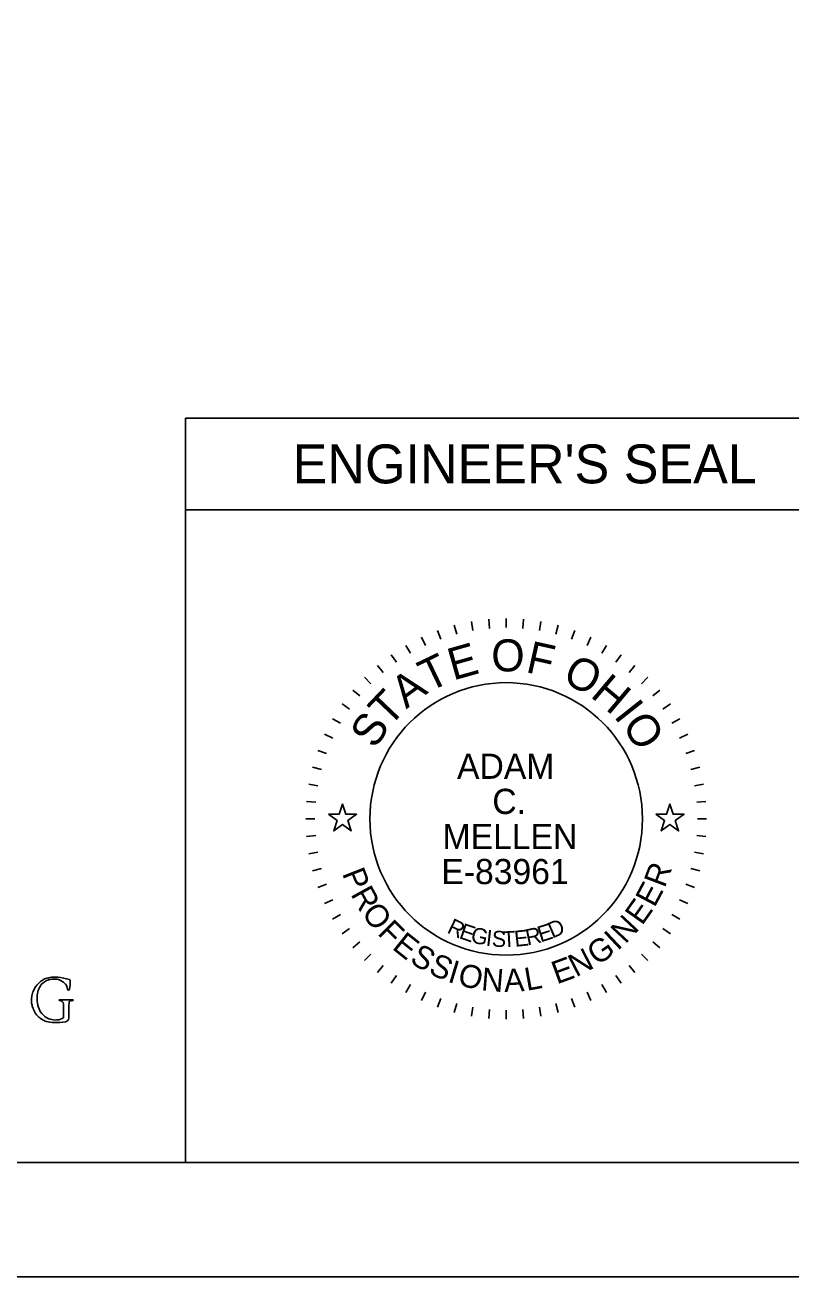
# Model space of a CAD drawing. Extents: x 0 to 34, y 0 to 22.
# Drawn here: x 6.65 to 9.99, y 0 to 5.47 of the extents above; entities that cross this region are included whole.
import ezdxf

# ---------------------------------------------------------------- set-up
doc = ezdxf.new("R2010")
doc.units = 0
for name, color, linetype in [('SH_Border', 7, 'Continuous'), ('SH_Cut_Line', 7, 'Continuous'), ('SH_Data', 7, 'Continuous'), ('SH_Seal', 7, 'Continuous'), ('SH_Text', 7, 'Continuous')]:
    doc.layers.add(name, color=color, linetype=linetype)

msp = doc.modelspace()

# ---------------------------------------------------------------- linework, layer by layer
at = {"layer": 'SH_Border'}
msp.add_lwpolyline([(1.5, 21.5), (33.5, 21.5), (33.5, 0.5), (1.5, 0.5)], close=True, dxfattribs=at)
at = {"layer": 'SH_Cut_Line'}
msp.add_lwpolyline([(0, 0), (34, 0), (34, 22), (0, 22)], close=True, dxfattribs=at)
at = {"layer": 'SH_Data'}
for p, q in [((10.15, 3.75), (7.35, 3.75)), ((7.35, 3.75), (7.35, 0.5)), ((10.15, 3.35), (7.35, 3.35)), ((10.15, 0.5), (7.35, 0.5))]:
    msp.add_line(p, q, dxfattribs=at)
at = {"layer": 'SH_Seal'}
for p, q in [((8.5235, 2.8452), (8.5339, 2.8065)), ((8.5981, 2.8617), (8.605, 2.8223)), ((8.6737, 2.8717), (8.6772, 2.8318)), ((8.75, 2.875), (8.75, 2.835)), ((8.8263, 2.8717), (8.8228, 2.8318)), ((8.9019, 2.8617), (8.895, 2.8223)), ((8.9765, 2.8452), (8.9661, 2.8065)), ((8.3802, 2.793), (8.3971, 2.7568)), ((8.4507, 2.8222), (8.4644, 2.7846)), ((9.0493, 2.8222), (9.0356, 2.7846)), ((9.1198, 2.793), (9.1029, 2.7568)), ((8.3125, 2.7578), (8.3325, 2.7231)), ((9.1875, 2.7578), (9.1675, 2.7231)), ((8.2481, 2.7168), (8.2711, 2.684)), ((9.2519, 2.7168), (9.2289, 2.684)), ((8.1876, 2.6703), (8.2133, 2.6396)), ((9.3124, 2.6703), (9.2867, 2.6396)), ((8.1313, 2.6187), (8.1596, 2.5904)), ((9.3687, 2.6187), (9.3404, 2.5904)), ((8.0797, 2.5624), (8.1104, 2.5367)), ((9.4203, 2.5624), (9.3896, 2.5367)), ((8.0332, 2.5019), (8.066, 2.4789)), ((9.4668, 2.5019), (9.434, 2.4789)), ((7.9922, 2.4375), (8.0269, 2.4175)), ((9.5078, 2.4375), (9.4731, 2.4175)), ((7.957, 2.3698), (7.9932, 2.3529)), ((9.543, 2.3698), (9.5068, 2.3529)), ((7.9278, 2.2993), (7.9654, 2.2856)), ((9.5722, 2.2993), (9.5346, 2.2856)), ((7.9048, 2.2265), (7.9435, 2.2161)), ((9.5952, 2.2265), (9.5565, 2.2161)), ((7.8883, 2.1519), (7.9277, 2.145)), ((9.6117, 2.1519), (9.5723, 2.145)), ((7.8783, 2.0763), (7.9182, 2.0728)), ((9.6217, 2.0763), (9.5818, 2.0728)), ((7.875, 2), (7.915, 2)), ((9.625, 2), (9.585, 2)), ((7.8783, 1.9237), (7.9182, 1.9272)), ((9.6217, 1.9237), (9.5818, 1.9272)), ((7.8883, 1.8481), (7.9277, 1.855)), ((9.6117, 1.8481), (9.5723, 1.855)), ((7.9048, 1.7735), (7.9435, 1.7839)), ((9.5952, 1.7735), (9.5565, 1.7839)), ((7.9278, 1.7007), (7.9654, 1.7144)), ((9.5722, 1.7007), (9.5346, 1.7144)), ((7.957, 1.6302), (7.9932, 1.6471)), ((9.543, 1.6302), (9.5068, 1.6471)), ((7.9922, 1.5625), (8.0269, 1.5825)), ((9.5078, 1.5625), (9.4731, 1.5825)), ((8.0332, 1.4981), (8.066, 1.5211)), ((9.4668, 1.4981), (9.434, 1.5211)), ((8.0797, 1.4376), (8.1104, 1.4633)), ((9.4203, 1.4376), (9.3896, 1.4633)), ((8.1313, 1.3813), (8.1596, 1.4096)), ((9.3687, 1.3813), (9.3404, 1.4096)), ((8.1876, 1.3297), (8.2133, 1.3604)), ((8.2481, 1.2832), (8.2711, 1.316)), ((9.2519, 1.2832), (9.2289, 1.316)), ((9.3124, 1.3297), (9.2867, 1.3604)), ((8.3125, 1.2422), (8.3325, 1.2769)), ((9.1875, 1.2422), (9.1675, 1.2769)), ((8.3802, 1.207), (8.3971, 1.2432)), ((8.4507, 1.1778), (8.4644, 1.2154)), ((9.0493, 1.1778), (9.0356, 1.2154)), ((9.1198, 1.207), (9.1029, 1.2432)), ((8.5235, 1.1548), (8.5339, 1.1935)), ((8.5981, 1.1383), (8.605, 1.1777)), ((8.6737, 1.1283), (8.6772, 1.1682)), ((8.75, 1.125), (8.75, 1.165)), ((8.8263, 1.1283), (8.8228, 1.1682)), ((8.9019, 1.1383), (8.895, 1.1777)), ((8.9765, 1.1548), (8.9661, 1.1935))]:
    msp.add_line(p, q, dxfattribs=at)
for points in [[(7.9736, 2.02), (8.0205, 2.02), (8.035, 2.0645), (8.0495, 2.02), (8.0964, 2.02), (8.0585, 1.9924), (8.073, 1.9478), (8.035, 1.9754), (7.997, 1.9478), (8.0115, 1.9924)], [(9.4036, 2.02), (9.4505, 2.02), (9.465, 2.0645), (9.4795, 2.02), (9.5264, 2.02), (9.4885, 1.9924), (9.503, 1.9478), (9.465, 1.9754), (9.427, 1.9478), (9.4415, 1.9924)]]:
    msp.add_lwpolyline(points, close=True, dxfattribs=at)
msp.add_circle((8.75, 2), 0.595, dxfattribs=at)
at = {"layer": 'SH_Text'}
for p, q in [((6.8573, 1.2104), (6.7998, 1.2104)), ((6.8165, 1.1919), (6.8165, 1.1358)), ((6.8402, 1.1303), (6.8402, 1.1778))]:
    msp.add_line(p, q, dxfattribs=at)
for centre, radius, start, end in [((6.7912, 1.2017), 0.1159, 135.2994, 157.2066), ((6.7747, 1.2302), 0.0714, 147.5385, 165.5071), ((6.7705, 1.2222), 0.0867, 107.613, 135.2994), ((6.7747, 1.2302), 0.0714, 116.7026, 147.5385), ((6.7691, 1.2414), 0.0589, 93.5922, 116.7026), ((6.772, 1.2175), 0.0916, 90.0889, 107.613), ((6.7762, 1.1283), 0.1722, 87.6816, 93.5922), ((6.7722, 1.0551), 0.254, 85.6243, 90.0889), ((6.7811, 1.2496), 0.0509, 59.809, 87.6816), ((6.773, 1.0659), 0.2432, 73.3259, 85.6243), ((6.7478, 1.1923), 0.1171, 52.0865, 59.809), ((6.7962, 1.2544), 0.0384, 2.9119, 52.0865), ((6.8414, 1.2941), 0.00494, 1.0594, 73.3259), ((6.6437, 1.2905), 0.2027, 350.1479, 1.0594), ((6.7684, 1.2065), 0.0913, 176.8679, 187.4835), ((6.8177, 1.2038), 0.1407, 167.8164, 176.8679), ((6.7472, 1.2191), 0.0685, 158.442, 167.8164), ((6.7912, 1.2017), 0.1159, 157.2066, 158.442), ((6.8436, 1.2139), 0.1422, 167.8795, 178.2857), ((6.7993, 1.2152), 0.0979, 178.2857, 190.5998), ((6.8104, 1.221), 0.1082, 165.5071, 167.8795), ((6.7998, 1.2084), 0.00203, 90, 277.32), ((6.8019, 1.1919), 0.0146, 0, 97.32), ((6.839, 1.2566), 0.00447, 182.9119, 350.1479), ((6.8475, 1.199), 0.00585, 114.8736, 172.0456), ((6.8552, 1.1824), 0.0242, 95.8947, 114.8736), ((6.8706, 1.0334), 0.174, 94.3316, 95.8947), ((6.8573, 1.2086), 0.00179, 274.3316, 90), ((6.7562, 1.2049), 0.0789, 187.4835, 199.5864), ((6.8236, 1.2289), 0.1505, 199.5864, 208.6065), ((6.763, 1.1959), 0.0815, 208.6065, 229.3453), ((6.934, 1.2404), 0.2349, 190.5998, 194.5022), ((6.7857, 1.202), 0.0818, 194.5022, 227.8932), ((6.9991, 1.1778), 0.1589, 172.0456, 180), ((6.7848, 1.2213), 0.1149, 229.3453, 237.7571), ((6.76, 1.182), 0.0686, 237.7571, 254.2366), ((6.7815, 1.1974), 0.0755, 227.8932, 268.7516), ((6.7779, 1.2453), 0.1343, 254.2366, 269.1033), ((6.7806, 1.4165), 0.3056, 269.1033, 278.6618), ((6.7815, 1.1969), 0.075, 268.7516, 293.6665), ((6.8083, 1.1358), 0.00829, 293.6665, 0), ((6.8242, 1.1303), 0.016, 278.6618, 0)]:
    msp.add_arc(centre, radius, start, end, dxfattribs=at)

# ---------------------------------------------------------------- texts
at = {"layer": 'SH_Data'}
msp.add_text("ENGINEER'S SEAL", height=0.17, dxfattribs=at).set_placement((7.8176, 3.465))
at = {"layer": 'SH_Seal'}
for s, height, rotation, p in [('E', 0.14, 15.7571, (8.5184, 2.6038)), ('O', 0.14, 359.7812, (8.6847, 2.6443)), ('F', 0.14, 347.4362, (8.8311, 2.6417)), ('T', 0.14, 25.7167, (8.4116, 2.5518)), ('O', 0.14, 332.2586, (8.9898, 2.6015)), ('A', 0.14, 36.4747, (8.3134, 2.4781)), ('H', 0.14, 319.9136, (9.1132, 2.5361)), ('T', 0.14, 46.4344, (8.2383, 2.3964)), ('I', 0.14, 308.367, (9.2165, 2.4483)), ('S', 0.14, 57.1924, (8.1781, 2.3014)), ('O', 0.14, 303.1491, (9.2521, 2.4089)), ('R', 0.1, 69.2322, (9.4419, 1.6954)), ('P', 0.1, 291.494, (8.0323, 1.7621)), ('R', 0.1, 298.7311, (8.069, 1.6717)), ('E', 0.1, 61.9951, (9.3976, 1.6098)), ('E', 0.1, 54.758, (9.3433, 1.5314)), ('O', 0.1, 306.4666, (8.1155, 1.5883)), ('F', 0.1, 314.7068, (8.1843, 1.4983)), ('R', 0.07, 334.487, (8.4875, 1.5051)), ('E', 0.07, 341.04, (8.5406, 1.4801)), ('E', 0.07, 17.6836, (8.8998, 1.4602)), ('D', 0.07, 23.3052, (8.951, 1.477)), ('N', 0.1, 47.0224, (9.2702, 1.4508)), ('E', 0.1, 321.4393, (8.2478, 1.4348)), ('G', 0.07, 347.4752, (8.5914, 1.4618)), ('I', 0.07, 353.7858, (8.6591, 1.4468)), ('S', 0.07, 356.8926, (8.6858, 1.4429)), ('T', 0.07, 3.0061, (8.7357, 1.4387)), ('E', 0.07, 6.0117, (8.7889, 1.4412)), ('R', 0.07, 11.9184, (8.8425, 1.4474)), ('G', 0.1, 35.0469, (9.1481, 1.357)), ('I', 0.1, 43.287, (9.2368, 1.4214)), ('S', 0.1, 328.6764, (8.3243, 1.3752)), ('N', 0.1, 27.3113, (9.0545, 1.3075)), ('S', 0.1, 335.9134, (8.4064, 1.3266)), ('I', 0.1, 343.1505, (8.4906, 1.2897)), ('O', 0.1, 346.8859, (8.5339, 1.2751)), ('E', 0.1, 20.0742, (8.9712, 1.277)), ('N', 0.1, 355.1261, (8.6388, 1.2517)), ('A', 0.1, 2.8617, (8.7423, 1.2437)), ('L', 0.1, 10.0987, (8.8394, 1.249))]:
    msp.add_text(s, height=height, rotation=rotation, dxfattribs=at).set_placement(p)
for s, p in [('ADAM', (8.5353, 2.1749)), ('C.', (8.6894, 2.0216)), ('MELLEN', (8.4722, 1.8684)), ('E-83961', (8.4667, 1.7151))]:
    msp.add_text(s, height=0.11, dxfattribs=at).set_placement(p)

doc.saveas('drawing.dxf')
